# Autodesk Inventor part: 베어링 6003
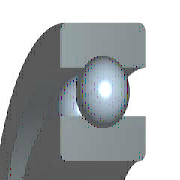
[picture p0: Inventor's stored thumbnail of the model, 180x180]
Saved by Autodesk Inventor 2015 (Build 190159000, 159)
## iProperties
Created: 2012-02
Part Number: 베어링 6003
Material: 강철, 연강
Description: 깊은 그루브 볼 베어링
Document SubType Name: Modeling
Standard: KS B 2023
Designer: mduedu
Standards Organization: KS
Language: ko-KR
Size Designation: 6003 - 17 x 35 x 10
Categories: <MemberInstance><Categories><Category DisplayName="샤프트 부품" InternalName="7f7aeb1f-a693-4053-b835-cee3144e0d98" Mnemonic="SHFT"><Category DisplayName="베어링" Inter
Density: 7.86 g/cm^3
Appearance: 주황색
Mass: 39.0276 g
Surface Area: 48.7538 cm^2
Volume: 4.96535 cm^3
IsCustomPart: 1
Author: mduedu
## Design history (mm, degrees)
sketch "스케치" dims "d0" = 4.68 (= -0.26 x WD + 0.26 x BD)
  geometry: L1 (2.66, 13)-(7.34, 13); L2 (5, 13)-(5, 10.66); L3 (5, 13)-(5, 15.34); L4 (3.261, 11.434)-(0, 11.434); L5 (0, 8.5)-(10, 8.5); L6 (3.261, 14.566)-(0, 14.566); L7 (0, 17.5)-(10, 17.5); L8 (10, 8.5)-(10, 11.434); L9 (6.739, 11.434)-(10, 11.434); L10 (6.739, 14.566)-(10, 14.566); L11 (10, 17.5)-(10, 14.566); L12 (-1.4, 0)-(8.4, 0) reference; L13 (0, -0.3)-(0, 5.3) reference
  constraints: 22 end point, 4 point on line, 2 collinear, 2 perpendicular, 2 symmetric about line, 1 midpoint, 1 parallel, 14 other
  dimensions: "d9" = 17 diameter of L5 L12 (= WD); "d11" = 35 diameter of L7 L12 (= BD); "d12" = 10 distance between parallel lines of L8 L13 (= KB); "d13" = 22.868 diameter of L9 L12 (= 0.326 x BD + 0.674 x WD)
revolve "본체" stored, may be unused: angle "d6" = 90 deg
revolve "볼" stored, may be unused: angle "d7" = 90 deg
pattern_circular "IDS_ARRAYBALL[SIMPL:T]" dims angle "d3" = 360 deg
body "Solid1"
fillet "모깎기1" dims "d1" = 0.3 (= KRS)
other parameters: "WD" = 17 [user parameter; used in 5 equation terms], "BD" = 35 [user parameter; used in 5 equation terms], "KB" = 10 [user parameter; used in 1 equation term], "KRS" = 0.3 [user parameter; used in 1 equation term], "d4" = 0, "d5" = 0, "d8" = 0, "d14" = 0, "d15" = 0, "BBA" = 0 [user parameter], "BC0" = 3250000 [user parameter], "BC" = 6050000 [user parameter], "BR" = 17.5 (= 0.5 x BD) [user parameter], "WR" = 8.5 (= 0.5 x WD) [user parameter]
